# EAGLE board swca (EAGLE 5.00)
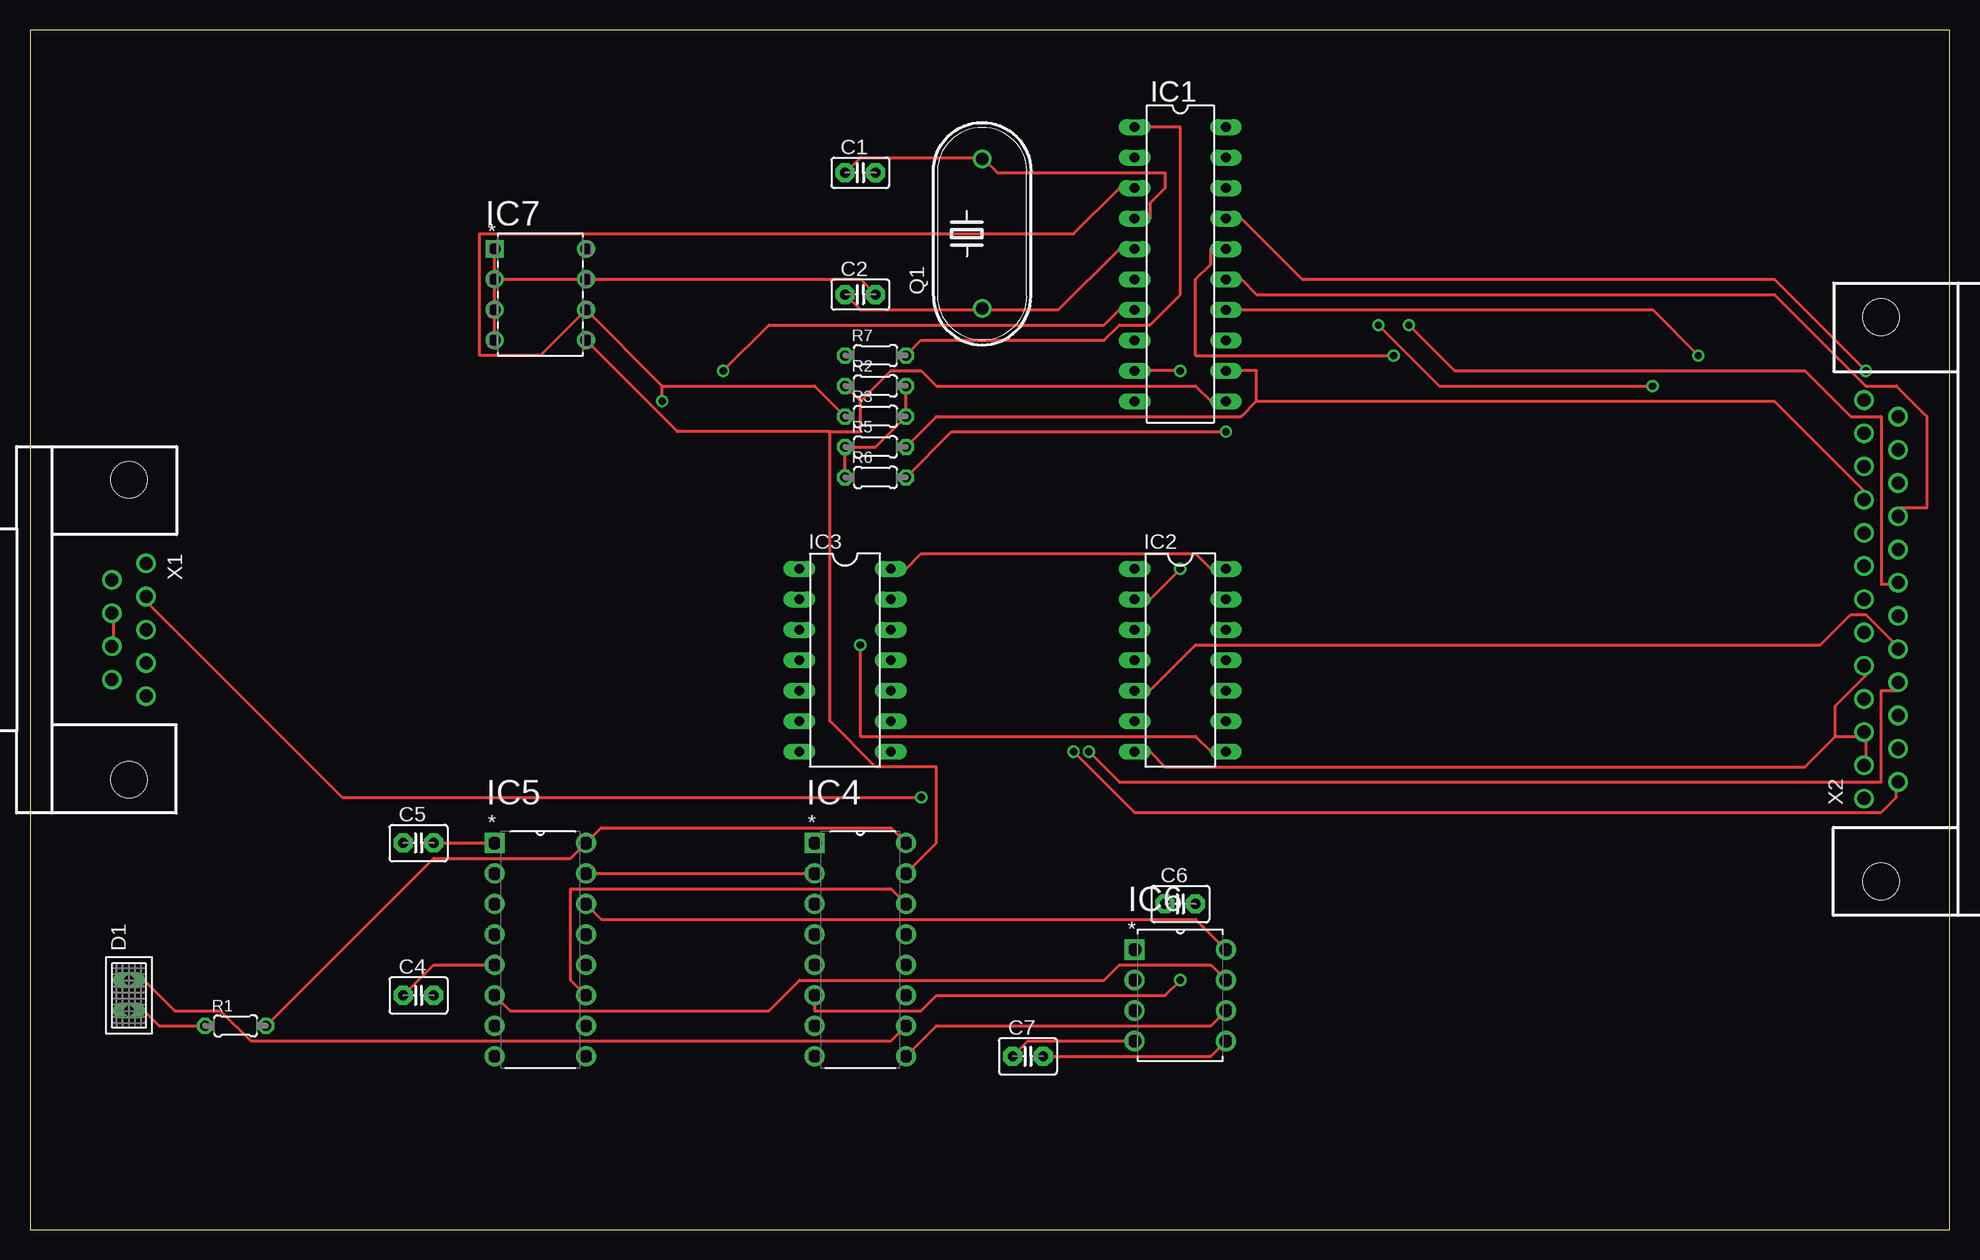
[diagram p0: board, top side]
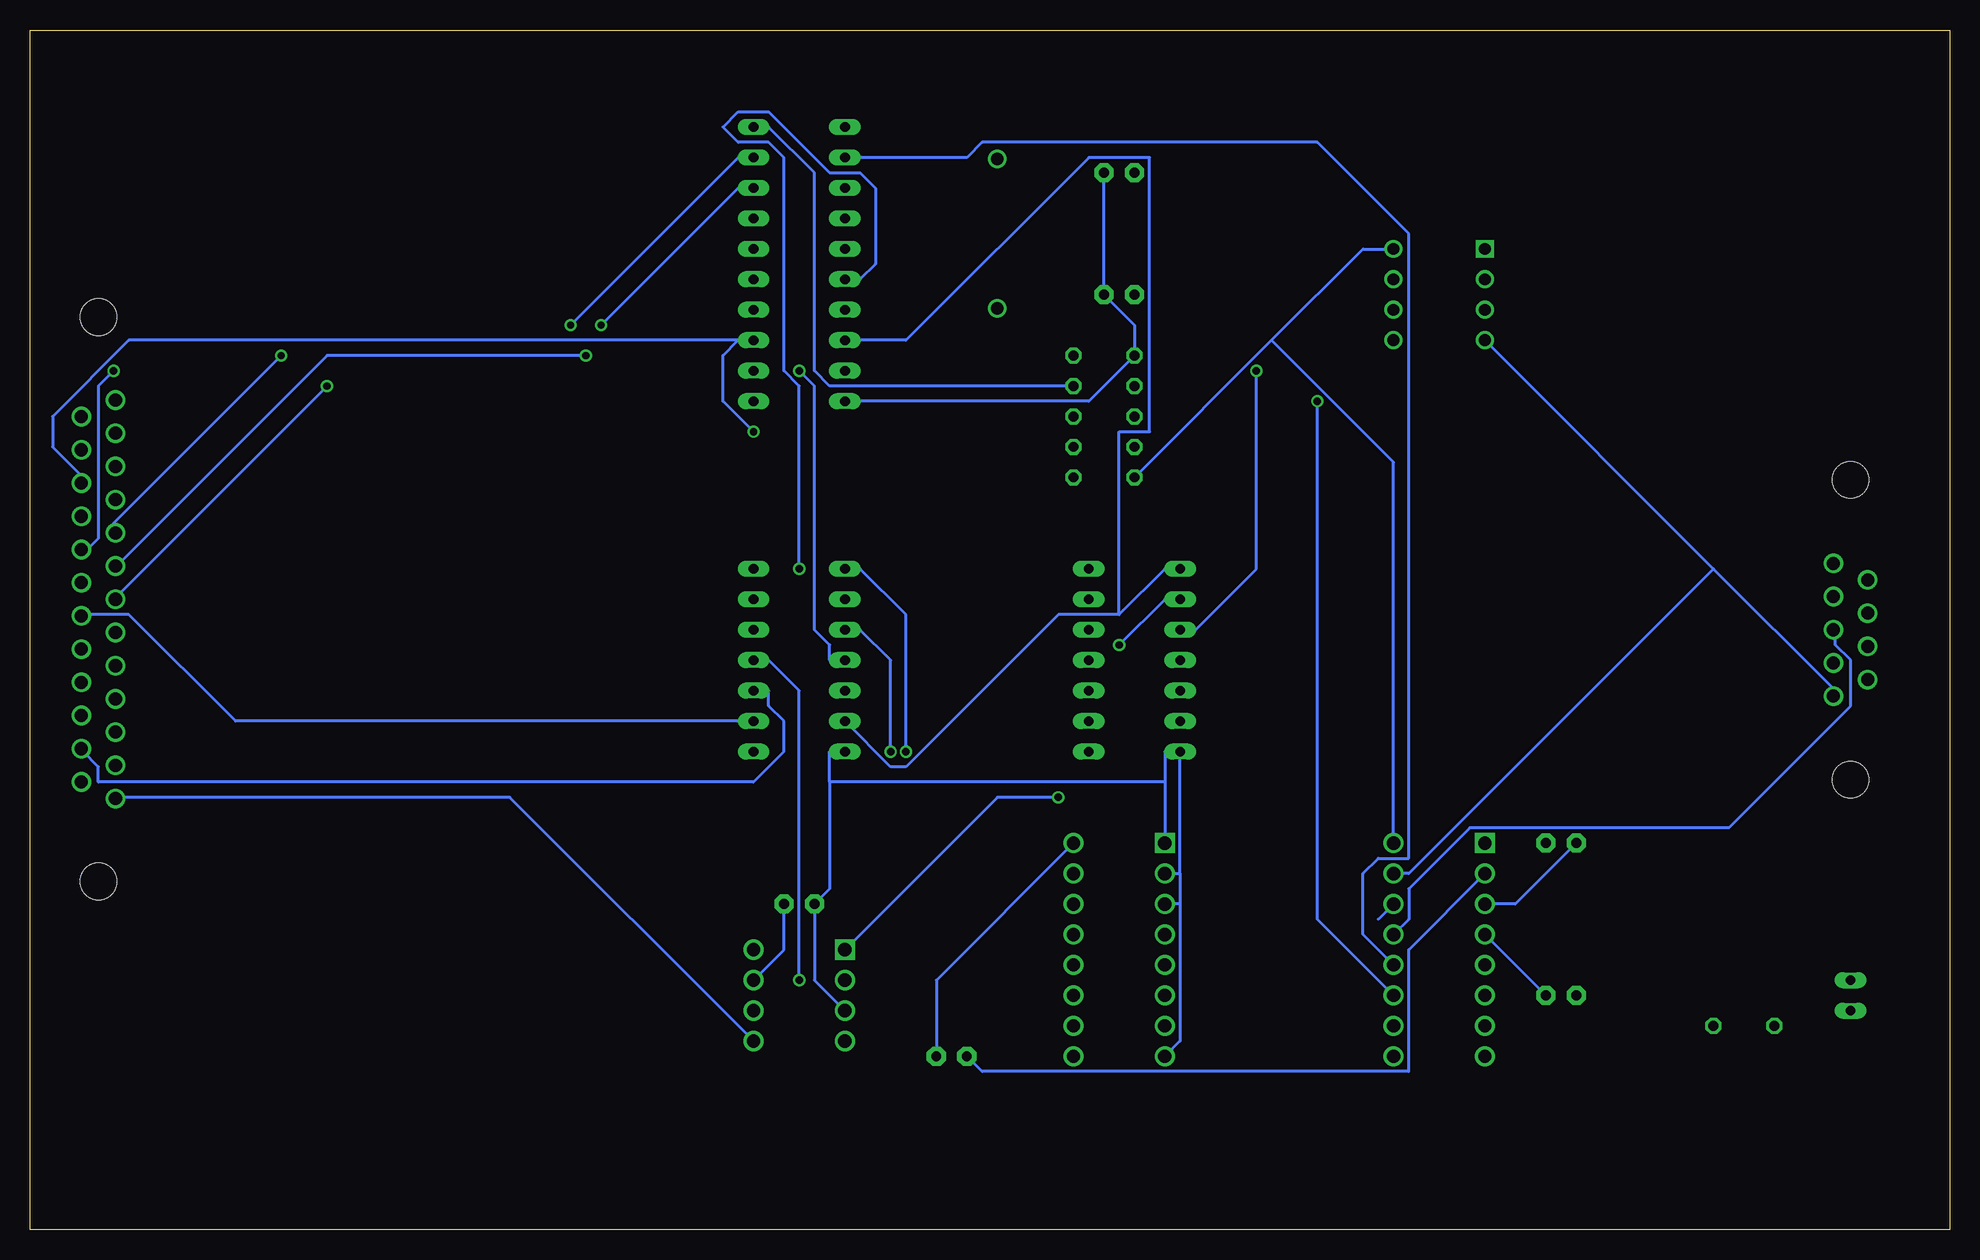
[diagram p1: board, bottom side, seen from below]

Size 160 x 100 mm. Coordinates in mm from the lower left corner, seen from the top.
Outline: 0,0 160,0 160,100 0,100 0,0
Copper layers (1*16): Top 0.035mm / dielectric 1.5mm / Bottom 0.035mm
Design rules "default": minimum track width 10mil, minimum drill 24mil, track to track 8mil, track to pad 8mil, pad to pad 8mil, via to via 8mil, smd to smd 8mil, copper to edge 40mil, drill to drill 8mil, minimum pad ring 10mil, minimum via ring 8mil, stop-mask expansion 4mil, vias tented up to drill 0mil, thermal gap 10mil

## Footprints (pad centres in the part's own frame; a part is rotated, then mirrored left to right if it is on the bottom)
C2.5-2 = drill 0.813 pad 1.6 octagon: 1 -1.27,0; 2 1.27,0
C2.5-3 = drill 0.813 pad 1.6 octagon: 1 -1.27,0; 2 1.27,0
U57X32 = drill 0.813 long: A -1.27,0; K 1.27,0
DIL20 = drill 0.813 long: 1 -11.43,-3.81; 2 -8.89,-3.81; 3 -6.35,-3.81; 4 -3.81,-3.81; 5 -1.27,-3.81; 6 1.27,-3.81; 7 3.81,-3.81; 8 6.35,-3.81; 9 8.89,-3.81; 10 11.43,-3.81; 11 11.43,3.81; 12 8.89,3.81; 13 6.35,3.81; 14 3.81,3.81; 15 1.27,3.81; 16 -1.27,3.81; 17 -3.81,3.81; 18 -6.35,3.81; 19 -8.89,3.81; 20 -11.43,3.81
DIL14 = drill 0.813 long: 1 -7.62,-3.81; 2 -5.08,-3.81; 3 -2.54,-3.81; 4 0,-3.81; 5 2.54,-3.81; 6 5.08,-3.81; 7 7.62,-3.81; 8 7.62,3.81; 9 5.08,3.81; 10 2.54,3.81; 11 0,3.81; 12 -2.54,3.81; 13 -5.08,3.81; 14 -7.62,3.81
DIP254P762X508-16 = drill 1.118 square: 1 -7.62,17.78 | drill 1.118 round: 2 -7.62,15.24; 3 -7.62,12.7; 4 -7.62,10.16; 5 -7.62,7.62; 6 -7.62,5.08; 7 -7.62,2.54; 8 -7.62,0; 9 0,0; 10 0,2.54; 11 0,5.08; 12 0,7.62; 13 0,10.16; 14 0,12.7; 15 0,15.24; 16 0,17.78
DIP254P762X533-8 = drill 1.118 square: 1 -7.62,7.62 | drill 1.118 round: 2 -7.62,5.08; 3 -7.62,2.54; 4 -7.62,0; 5 0,0; 6 0,2.54; 7 0,5.08; 8 0,7.62
DIP254P762X533-8' = drill 0.991 square: 1 -7.62,7.62 | drill 0.991 round: 2 -7.62,5.08; 3 -7.62,2.54; 4 -7.62,0; 5 0,0; 6 0,2.54; 7 0,5.08; 8 0,7.62
HC33U-V = drill 1.016 round: 1 -6.223,0; 2 6.223,0
0204/5 = drill 0.813 octagon: 1 -2.54,0; 2 2.54,0
H3M09RA = drill 1.092 round: 1 -5.537,1.422; 2 -2.769,1.422; 3 0,1.422; 4 2.769,1.422; 5 5.537,1.422; 6 -4.153,-1.422; 7 -1.384,-1.422; 8 1.384,-1.422; 9 4.153,-1.422 | hole 3.048: -12.497,0; 12.497,0
H3M25RA = drill 1.092 round: 1 -16.612,1.422; 2 -13.843,1.422; 3 -11.074,1.422; 4 -8.306,1.422; 5 -5.537,1.422; 6 -2.769,1.422; 7 0,1.422; 8 2.769,1.422; 9 5.537,1.422; 10 8.306,1.422; 11 11.074,1.422; 12 13.843,1.422; 13 16.612,1.422; 14 -15.227,-1.422; 15 -12.459,-1.422; 16 -9.69,-1.422; 17 -6.921,-1.422; 18 -4.153,-1.422; 19 -1.384,-1.422; 20 1.384,-1.422; 21 4.153,-1.422; 22 6.921,-1.422; 23 9.69,-1.422; 24 12.459,-1.422; 25 15.227,-1.422 | hole 3.048: -23.52,0; 23.52,0

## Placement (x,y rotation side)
C1  [C2.5-2]  69.21,88.1 0 top
C2  [C2.5-2]  69.21,77.94 0 top
C4  [C2.5-3]  32.38,19.52 0 top
C5  [C2.5-3]  32.38,32.22 0 top
C6  [C2.5-3]  95.88,27.14 0 top
C7  [C2.5-3]  83.18,14.44 0 top
D1  U57X32  [U57X32]  8.25,19.52 90 top
IC1  AT89C2051P  [DIL20]  95.88,80.48 270 top
IC2  74LS14N  [DIL14]  95.88,47.46 270 top
IC3  74LS86N  [DIL14]  67.94,47.46 270 top
IC4  PCF8574AN  [DIP254P762X508-16]  73.02,14.44 0 top
IC5  MAX232N  [DIP254P762X508-16]  46.35,14.44 0 top
IC6  ADG417BNZ  [DIP254P762X533-8]  99.69,15.71 0 top
IC7  24LC04B-I/P  [DIP254P762X533-8']  46.35,74.13 0 top
Q1  [HC33U-V]  79.37,83.02 90 top
R1  [0204/5]  17.14,16.98 0 top
R2  [0204/5]  70.48,70.32 0 top
R3  [0204/5]  70.48,67.78 0 top
R5  [0204/5]  70.48,65.24 0 top
R6  [0204/5]  70.48,62.7 0 top
R7  [0204/5]  70.48,72.86 0 top
X1  D-SUB9-H3M09RA  [H3M09RA]  8.25,50 270 top
X2  D-SUB25-H3M25RA  [H3M25RA]  154.3,52.54 90 top

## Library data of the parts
C1 C2 C4-C7 = capacitor-wima
D1 = led
IC1 = atmel
IC2 IC3 = 74xx-us
IC4 = TI-PCF8574AN; MPN: PCF8574AN; OC_FARNELL: 1703443; OC_NEWARK: 75C5234; PACKAGE: PDIP-16; SUPPLIER: Texas Instruments
IC5 = MAX232; MPN: MAX232N; OC_FARNELL: 1470445; OC_NEWARK: 59K8220; PACKAGE: PDIP-16; SUPPLIER: Texas Instruments
IC6 = DG417; MPN: ADG417BNZ; OC_FARNELL: 1311279; OC_NEWARK: 59K1257; PACKAGE: PDIP-8; SUPPLIER: Analog Devices
IC7 = 24LC04B dip; MPN: 24LC04B-I/P; OC_FARNELL: 1196811; OC_NEWARK: 62K0576; PACKAGE: DIP-8; SUPPLIER: Microchip
Q1 = crystal
R1-R3 R5-R7 = resistor
X1 X2 = con-thomas-betts

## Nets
+5V: C7.2 IC1.20 IC4.16 IC5.16 IC6.5 IC7.8 R1.2 R2.2 R3.2 R5.1 R6.1 X2.1
GND: C1.2 C2.2 C6.1 IC1.10 IC2.7 IC3.7 IC4.1 IC4.2 IC4.3 IC4.8 IC5.15 IC6.3 IC7.1 IC7.2 IC7.3 IC7.4 IC7.7 R7.1 X1.5 X2.2 X2.3 X2.5
MAX232: IC2.11 IC4.6
N$1: IC1.8 IC2.6 IC3.1
N$2: IC2.8 IC3.2
N$3: IC1.7 IC3.3
N$4: IC1.2 IC5.12
N$5: IC1.6 IC2.2
N$6: IC1.9 IC2.4
N$7: C1.1 IC1.4 Q1.2
N$8: C2.1 IC1.5 Q1.1
N$9: IC4.9 IC6.6
N$10: IC1.11 IC4.15 IC7.5 R2.1
N$11: IC1.3 IC4.14 IC5.11 IC7.6 R3.1
N$12: C4.2 IC5.4
N$13: C4.1 IC5.5
N$14: C5.2 IC5.1
N$15: C6.2 IC5.6 IC6.7
N$16: C5.1 IC5.3
N$18: C7.1 IC5.2 IC6.4
N$19: IC5.13 X1.3
N$20: IC6.1 X1.2
N$21: IC5.14 IC6.8
N$23: X1.7 X1.8
N$25: D1.K IC4.10
N$26: D1.A R1.1
N$27: IC1.1 R7.2
N$30: IC2.10 X2.15
N$31: IC1.19 X2.20
N$32: IC1.18 X2.7
N$33: IC1.17 X2.21
N$34: IC1.16 X2.8
N$35: IC1.15 X2.22
N$36: IC1.14 X2.9
N$37: IC1.13 R6.2 X2.23
N$38: IC1.12 R5.2 X2.10
N$41: IC2.3 X2.17
N$42: IC2.1 X2.14
N$43: IC2.9 X2.19
N$44: IC2.5 X2.18
VCC: IC2.14 IC3.14

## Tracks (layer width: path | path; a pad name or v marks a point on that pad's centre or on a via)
+5V
  Top 0.254: R6.1 R5.1 70.48,65.24 R3.2 R2.2 | R1.2 33.65,30.95 45.08,30.95 IC5.16 47.62,33.49 71.75,33.49 IC4.16 | C7.2 98.42,14.44 IC6.5
  Bottom 0.254: IC7.8 48.89,81.75 56.51,74.13 | 56.51,74.13 R6.1 | R2.2 93.34,70.32 94.61,71.59 94.61,88.1 98.42,91.91 IC1.20 | IC6.5 120.01,36.03 153.03,36.03 X2.1 | IC4.16 84.45,20.79 C7.2 | 56.51,74.13 46.35,63.97 IC5.16
GND
  Top 0.254: IC7.4 IC7.3 IC7.2 | IC7.2 IC7.1 | IC7.2 IC7.7 69.21,79.21 C2.2 | IC5.15 IC4.2 | 153.03,41.11 153.03,38.57 X2.2 | 150.49,41.11 150.49,43.65 153.03,46.19 X2.5 | 150.49,41.11 153.03,41.11 | 153.03,41.11 X2.3 | 150.49,41.11 147.95,38.57 94.61,38.57 93.34,39.84 IC2.7
  Bottom 0.254: IC1.10 71.75,69.05 R7.1 67.94,75.4 C2.2 C1.2 | 19.68,55.08 IC7.4 | 19.68,55.08 9.52,44.92 X1.5 | 65.4,37.3 IC4.1 | 65.4,37.3 65.4,39.84 IC3.7 64.13,29.68 | IC4.8 64.13,15.71 64.13,27.14 | 64.13,29.68 64.13,27.14 | 64.13,27.14 IC4.3 | IC4.2 64.13,29.68 | 93.34,37.3 93.34,28.41 C6.1 94.61,20.79 IC6.3 | 93.34,37.3 93.34,39.84 IC2.7 | 65.4,37.3 93.34,37.3 | 19.68,55.08 45.08,29.68 IC5.15
MAX232  (via drill 0.61)
  Top 0.254: IC4.6 65.4,18.25 74.29,18.25 75.56,19.52 94.61,19.52 v95.88,20.79
  Bottom 0.254: v95.88,20.79 95.88,44.92 98.42,47.46 IC2.11
N$1
  Bottom 0.254: 69.21,51.27 65.4,55.08 IC3.1 | 69.21,51.27 74.29,51.27 86.99,38.57 88.26,38.57 IC2.6 | 69.21,51.27 69.21,66.51 66.67,66.51 66.67,89.37 71.75,89.37 86.99,74.13 IC1.8
N$2  (via drill 0.61)
  Top 0.254: v69.21,48.73 69.21,41.11 97.15,41.11 98.42,39.84 IC2.8
  Bottom 0.254: v69.21,48.73 65.4,52.54 IC3.2
N$3  (via drill 0.61)
  Top 0.254: v57.78,71.59 61.59,75.4 89.53,75.4 90.8,76.67 IC1.7
  Bottom 0.254: v57.78,71.59 57.78,55.08 62.86,50 IC3.3
N$4
  Bottom 0.254: IC5.12 48.89,24.6 48.89,29.68 47.62,30.95 45.08,30.95 45.08,83.02 52.7,90.64 80.64,90.64 81.91,89.37 IC1.2
N$5  (via drill 0.61)
  Top 0.254: v95.88,55.08 93.34,52.54 IC2.2
  Bottom 0.254: v95.88,55.08 95.88,70.32 97.15,71.59 97.15,89.37 98.42,90.64 100.96,90.64 102.23,91.91 100.96,93.18 98.42,93.18 93.34,88.1 90.8,88.1 89.53,86.83 89.53,80.48 90.8,79.21 IC1.6
N$6  (via drill 0.61)
  Top 0.254: v95.88,71.59 IC1.9
  Bottom 0.254: v95.88,71.59 94.61,70.32 94.61,50 93.34,48.73 93.34,47.46 IC2.4
N$7
  Top 0.254: 79.37,89.37 80.64,88.1 94.61,88.1 94.61,86.83 93.34,85.56 93.34,84.29 IC1.4 | C1.1 69.21,89.37 79.37,89.37 | 79.37,89.37 Q1.2
N$8
  Top 0.254: 79.37,76.67 85.72,76.67 90.8,81.75 IC1.5 | C2.1 69.21,76.67 79.37,76.67 | 79.37,76.67 Q1.1
N$9
  Top 0.254: IC4.9 75.56,16.98 98.42,16.98 IC6.6
N$10
  Top 0.254: 69.21,69.05 R2.1 | 69.21,69.05 69.21,66.51 66.67,66.51 | 66.67,66.51 53.97,66.51 IC7.5 | 69.21,69.05 71.75,71.59 74.29,71.59 75.56,70.32 97.15,70.32 98.42,69.05 IC1.11 | IC4.15 75.56,32.22 75.56,38.57 70.48,38.57 66.67,42.38 66.67,66.51
N$11  (via drill 0.61)
  Top 0.254: IC5.11 45.08,20.79 45.08,28.41 71.75,28.41 IC4.14 | R3.1 65.4,70.32 52.7,70.32 | 52.7,70.32 IC7.6 42.54,72.86 37.46,72.86 37.46,83.02 86.99,83.02 90.8,86.83 IC1.3 | v52.7,69.05 52.7,70.32
  Bottom 0.254: IC5.11 52.7,25.87 v52.7,69.05
N$12
  Bottom 0.254: C4.2 IC5.4
N$13
  Top 0.254: C4.1 33.65,22.06 IC5.5
N$14
  Top 0.254: C5.2 IC5.1
N$15
  Top 0.254: IC5.6 40,18.25 61.59,18.25 64.13,20.79 89.53,20.79 90.8,22.06 98.42,22.06 IC6.7
  Bottom 0.254: C6.2 97.15,23.33 IC6.7
N$16
  Bottom 0.254: C5.1 36.19,27.14 IC5.3
N$18
  Top 0.254: C7.1 83.18,15.71 IC6.4
  Bottom 0.254: IC5.2 45.08,23.33 45.08,13.17 80.64,13.17 C7.1
N$19
  Top 0.254: X1.3 9.52,50
  Bottom 0.254: IC5.13 45.08,25.87 45.08,28.41 40,33.49 18.41,33.49 8.25,43.65 8.25,47.46 9.52,48.73 9.52,50 X1.3
N$20  (via drill 0.61)
  Top 0.254: v74.29,36.03 26.03,36.03 9.52,52.54 X1.2
  Bottom 0.254: v74.29,36.03 79.37,36.03 IC6.1
N$21
  Top 0.254: IC6.8 97.15,25.87 47.62,25.87 IC5.14
  Bottom 0.254: IC5.14 47.62,25.87
N$23
  Top 0.254: X1.8 6.98,48.73 6.98,51.27 X1.7
N$25
  Top 0.254: IC4.10 71.75,15.71 18.41,15.71 15.87,18.25 12.06,18.25 9.52,20.79 D1.K
N$26
  Top 0.254: R1.1 10.79,16.98 9.52,18.25 D1.A
N$27
  Top 0.254: R7.2 74.29,74.13 89.53,74.13 90.8,75.4 93.34,75.4 95.88,77.94 95.88,91.91 IC1.1
N$30
  Bottom 0.254: IC2.10 98.42,44.92 98.42,43.65 97.15,42.38 97.15,39.84 99.69,37.3 154.3,37.3 154.3,38.57 155.57,39.84 X2.15
N$31  (via drill 0.61)
  Top 0.254: v114.93,75.4 118.74,71.59 147.95,71.59 151.76,67.78 154.3,67.78 154.3,53.81 155.57,53.81 X2.20
  Bottom 0.254: v114.93,75.4 100.96,89.37 IC1.19
N$32  (via drill 0.61)
  Top 0.254: v112.39,75.4 117.47,70.32 v135.25,70.32
  Bottom 0.254: v112.39,75.4 100.96,86.83 IC1.18 | v135.25,70.32 153.03,52.54 X2.7
N$33  (via drill 0.61)
  Top 0.254: v153.03,71.59 145.41,79.21 106.04,79.21 100.96,84.29 IC1.17
  Bottom 0.254: v153.03,71.59 154.3,70.32 154.3,57.62 155.57,56.35 X2.21
N$34  (via drill 0.61)
  Top 0.254: v113.66,72.86 97.15,72.86 97.15,79.21 98.42,80.48 98.42,81.75 IC1.16
  Bottom 0.254: v113.66,72.86 135.25,72.86 153.03,55.08 X2.8
N$35
  Top 0.254: IC1.15 100.96,79.21 102.23,77.94 145.41,77.94 153.03,70.32 155.57,70.32 158.11,67.78 158.11,60.16 155.57,60.16 X2.22
N$36  (via drill 0.61)
  Top 0.254: v139.06,72.86 135.25,76.67 IC1.14
  Bottom 0.254: v139.06,72.86 153.03,58.89 X2.9
N$37  (via drill 0.61)
  Top 0.254: R6.2 76.83,66.51 v99.69,66.51
  Bottom 0.254: v99.69,66.51 102.23,69.05 102.23,72.86 100.96,74.13 | 100.96,74.13 151.76,74.13 158.11,67.78 158.11,65.24 155.57,62.7 X2.23 | 100.96,74.13 IC1.13
N$38
  Top 0.254: R5.2 75.56,67.78 100.96,67.78 102.23,69.05 | 102.23,69.05 102.23,71.59 IC1.12 | 102.23,69.05 145.41,69.05 153.03,61.43 X2.10
N$41  (via drill 0.61)
  Top 0.254: v88.26,39.84 90.8,37.3 154.3,37.3 154.3,44.92 155.57,44.92 X2.17
  Bottom 0.254: v88.26,39.84 88.26,47.46 90.8,50 IC2.3
N$42  (via drill 0.61)
  Top 0.254: v86.99,39.84 92.07,34.76 154.3,34.76 155.57,36.03 155.57,37.3 X2.14
  Bottom 0.254: v86.99,39.84 86.99,51.27 90.8,55.08 IC2.1
N$43
  Bottom 0.254: IC2.9 142.87,42.38 151.76,51.27 155.57,51.27 X2.19
N$44
  Top 0.254: IC2.5 93.34,44.92 97.15,48.73 149.22,48.73 151.76,51.27 153.03,51.27 155.57,48.73 X2.18
VCC
  Top 0.254: IC3.14 73.02,55.08 74.29,56.35 97.15,56.35 98.42,55.08 IC2.14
